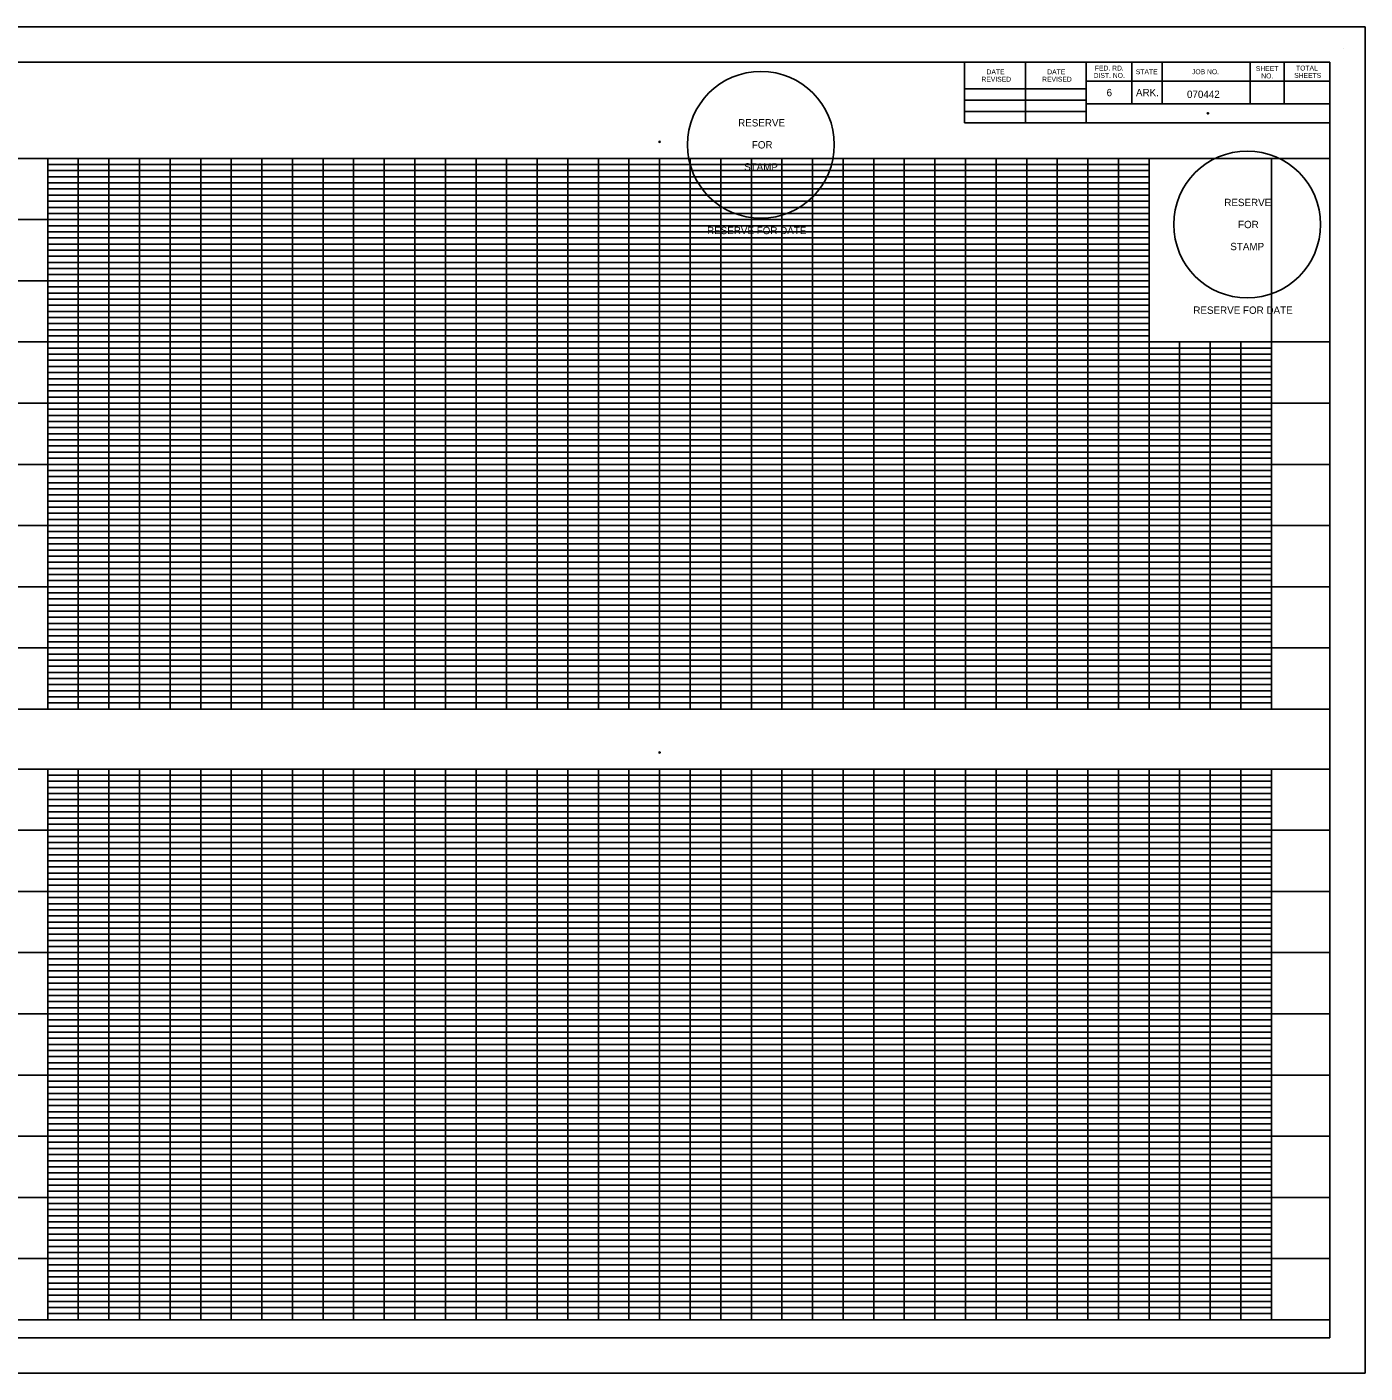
# Model space of a CAD drawing. Extents: x 1 to 1451078, y 0 to 2059437.
# Drawn here: x 1449985 to 1451078, y 2058337 to 2059437 of the extents above; entities that cross this region are included whole.
import ezdxf

# ---------------------------------------------------------------- set-up
doc = ezdxf.new("R2010")
doc.units = 0
for name, color, linetype in [('1', 7, 'Continuous'), ('G-ANNO-TEXT', 7, 'Continuous'), ('G-Border-Sheet', 7, 'Continuous'), ('G-Grid-Border-1', 7, 'Continuous'), ('G-Grid-Border-2', 7, 'Continuous'), ('G-Grid-Major-1', 7, 'Continuous'), ('G-Grid-Minor-1', 7, 'Continuous'), ('G-No Plot-Anchor', 7, 'Continuous'), ('G-No Plot-Stamp-1', 7, 'Continuous'), ('G-No Plot-Stamp-2', 7, 'Continuous'), ('G-Table-Major', 7, 'Continuous'), ('G-Table-Minor', 7, 'Continuous')]:
    doc.layers.add(name, color=color, linetype=linetype)

msp = doc.modelspace()

# ---------------------------------------------------------------- linework, layer by layer
at = {"layer": '1'}
msp.add_lwpolyline([(1451078.1, 2059436.5), (1449378.1, 2059436.5), (1449378.1, 2058336.5), (1451078.1, 2058336.5)], close=True, dxfattribs=at)
at = {"layer": 'G-ANNO-TEXT'}
msp.add_line((1451060.2, 2059419.2), (1451060.2, 2059419.2), dxfattribs=at)
at = {"layer": 'G-Border-Sheet'}
for p, q in [((1449453.9, 2059407.7), (1451049.3, 2059407.7)), ((1451049.3, 2058365.4), (1451049.3, 2059407.7)), ((1451049.3, 2058365.4), (1449453.9, 2058365.4))]:
    msp.add_line(p, q, dxfattribs=at)
at = {"layer": 'G-Grid-Border-1'}
for p, q in [((1450898.5, 2059329.1), (1449453.9, 2059329.1)), ((1451049.3, 2058879.1), (1449453.9, 2058879.1)), ((1451049.3, 2058830.1), (1449453.9, 2058830.1)), ((1451049.3, 2058380.1), (1449453.9, 2058380.1))]:
    msp.add_line(p, q, dxfattribs=at)
for points in [[(1450001.6, 2059329.1), (1450901.6, 2059329.1), (1450901.6, 2059179.1), (1451001.6, 2059179.1), (1451001.6, 2058879.1), (1450001.6, 2058879.1)], [(1450001.6, 2058830.1), (1451001.6, 2058830.1), (1451001.6, 2058380.1), (1450001.6, 2058380.1)]]:
    msp.add_lwpolyline(points, close=True, dxfattribs=at)
at = {"layer": 'G-Grid-Border-2'}
for p, q in [((1450501.6, 2059329.1), (1449453.9, 2059329.1)), ((1450501.6, 2059254.1), (1450501.6, 2059329.1)), ((1450501.6, 2059254.1), (1450501.6, 2059329.1)), ((1450651.6, 2059254.1), (1450651.6, 2059329.1)), ((1451049.3, 2059329.1), (1450651.6, 2059329.1)), ((1450651.6, 2059254.1), (1450651.6, 2059329.1)), ((1450501.6, 2059254.1), (1450651.6, 2059254.1)), ((1450501.6, 2059254.1), (1450651.6, 2059254.1)), ((1451001.6, 2058879.1), (1451001.6, 2059179.1)), ((1451049.3, 2058879.1), (1449453.9, 2058879.1)), ((1451049.3, 2058830.1), (1449453.9, 2058830.1)), ((1451001.6, 2058380.1), (1451001.6, 2058830.1)), ((1451049.3, 2058380.1), (1449453.9, 2058380.1))]:
    msp.add_line(p, q, dxfattribs=at)
for points in [[(1450001.6, 2059329.1), (1450501.6, 2059329.1), (1450501.6, 2059254.1), (1450651.6, 2059254.1), (1450651.6, 2059329.1), (1451001.6, 2059329.1), (1451001.6, 2058879.1), (1450001.6, 2058879.1)], [(1450001.6, 2058830.1), (1451001.6, 2058830.1), (1451001.6, 2058380.1), (1450001.6, 2058380.1)]]:
    msp.add_lwpolyline(points, close=True, dxfattribs=at)
msp.add_lwpolyline([(1451001.6, 2058830.1), (1451001.6, 2058380.1), (1449501.6, 2058380.1), (1449501.6, 2058830.1)], dxfattribs=at)
at = {"layer": 'G-Grid-Major-1'}
for p, q in [((1450001.6, 2058879.1), (1450001.6, 2059329.1)), ((1450051.6, 2058879.1), (1450051.6, 2059329.1)), ((1450101.6, 2058879.1), (1450101.6, 2059329.1)), ((1450151.6, 2058879.1), (1450151.6, 2059329.1)), ((1450201.6, 2058879.1), (1450201.6, 2059329.1)), ((1450251.6, 2058879.1), (1450251.6, 2059329.1)), ((1450301.6, 2058879.1), (1450301.6, 2059329.1)), ((1450351.6, 2058879.1), (1450351.6, 2059329.1)), ((1450401.6, 2058879.1), (1450401.6, 2059329.1)), ((1450451.6, 2058879.1), (1450451.6, 2059329.1)), ((1450501.6, 2058879.1), (1450501.6, 2059329.1)), ((1450551.6, 2058879.1), (1450551.6, 2059329.1)), ((1450601.6, 2058879.1), (1450601.6, 2059329.1)), ((1450651.6, 2058879.1), (1450651.6, 2059329.1)), ((1450701.6, 2058879.1), (1450701.6, 2059329.1)), ((1450751.6, 2058879.1), (1450751.6, 2059329.1)), ((1450801.6, 2058879.1), (1450801.6, 2059329.1)), ((1450851.6, 2058879.1), (1450851.6, 2059329.1)), ((1450901.6, 2058879.1), (1450901.6, 2059329.1)), ((1450901.6, 2059279.1), (1449901.6, 2059279.1)), ((1450901.6, 2059229.1), (1449901.6, 2059229.1)), ((1451049.3, 2059179.1), (1449901.6, 2059179.1)), ((1450951.6, 2058879.1), (1450951.6, 2059179.1)), ((1451049.3, 2059129.1), (1449901.6, 2059129.1)), ((1451049.3, 2059079.1), (1449901.6, 2059079.1)), ((1451049.3, 2059029.1), (1449901.6, 2059029.1)), ((1451049.3, 2058979.1), (1449901.6, 2058979.1)), ((1451049.3, 2058929.1), (1449901.6, 2058929.1)), ((1450051.6, 2058380.1), (1450051.6, 2058830.1)), ((1450101.6, 2058380.1), (1450101.6, 2058830.1)), ((1450151.6, 2058380.1), (1450151.6, 2058830.1)), ((1450201.6, 2058380.1), (1450201.6, 2058830.1)), ((1450251.6, 2058380.1), (1450251.6, 2058830.1)), ((1450301.6, 2058380.1), (1450301.6, 2058830.1)), ((1450351.6, 2058380.1), (1450351.6, 2058830.1)), ((1450401.6, 2058380.1), (1450401.6, 2058830.1)), ((1450451.6, 2058380.1), (1450451.6, 2058830.1)), ((1450501.6, 2058380.1), (1450501.6, 2058830.1)), ((1450551.6, 2058380.1), (1450551.6, 2058830.1)), ((1450601.6, 2058380.1), (1450601.6, 2058830.1)), ((1450651.6, 2058380.1), (1450651.6, 2058830.1)), ((1450701.6, 2058380.1), (1450701.6, 2058830.1)), ((1450751.6, 2058380.1), (1450751.6, 2058830.1)), ((1450801.6, 2058380.1), (1450801.6, 2058830.1)), ((1450851.6, 2058380.1), (1450851.6, 2058830.1)), ((1450901.6, 2058380.1), (1450901.6, 2058830.1)), ((1450951.6, 2058380.1), (1450951.6, 2058830.1)), ((1451049.3, 2058780.1), (1449901.6, 2058780.1)), ((1451049.3, 2058730.1), (1449901.6, 2058730.1)), ((1451049.3, 2058680.1), (1449901.6, 2058680.1)), ((1451049.3, 2058630.1), (1449901.6, 2058630.1)), ((1451049.3, 2058580.1), (1449901.6, 2058580.1)), ((1451049.3, 2058530.1), (1449901.6, 2058530.1)), ((1451049.3, 2058480.1), (1449901.6, 2058480.1)), ((1451049.3, 2058430.1), (1449901.6, 2058430.1))]:
    msp.add_line(p, q, dxfattribs=at)
at = {"layer": 'G-Grid-Minor-1'}
for p, q in [((1450901.6, 2059324.1), (1450001.6, 2059324.1)), ((1450026.6, 2058879.1), (1450026.6, 2059329.1)), ((1450076.6, 2058879.1), (1450076.6, 2059329.1)), ((1450126.6, 2058879.1), (1450126.6, 2059329.1)), ((1450176.6, 2058879.1), (1450176.6, 2059329.1)), ((1450226.6, 2058879.1), (1450226.6, 2059329.1)), ((1450276.6, 2058879.1), (1450276.6, 2059329.1)), ((1450326.6, 2058879.1), (1450326.6, 2059329.1)), ((1450376.6, 2058879.1), (1450376.6, 2059329.1)), ((1450426.6, 2058879.1), (1450426.6, 2059329.1)), ((1450476.6, 2058879.1), (1450476.6, 2059329.1)), ((1450526.6, 2058879.1), (1450526.6, 2059329.1)), ((1450576.6, 2058879.1), (1450576.6, 2059329.1)), ((1450626.6, 2058879.1), (1450626.6, 2059329.1)), ((1450676.6, 2058879.1), (1450676.6, 2059329.1)), ((1450726.6, 2058879.1), (1450726.6, 2059329.1)), ((1450776.6, 2058879.1), (1450776.6, 2059329.1)), ((1450826.6, 2058879.1), (1450826.6, 2059329.1)), ((1450876.6, 2058879.1), (1450876.6, 2059329.1)), ((1450901.6, 2059319.1), (1450001.6, 2059319.1)), ((1450901.6, 2059314.1), (1450001.6, 2059314.1)), ((1450901.6, 2059309.1), (1450001.6, 2059309.1)), ((1450901.6, 2059304.1), (1450001.6, 2059304.1)), ((1450901.6, 2059299.1), (1450001.6, 2059299.1)), ((1450901.6, 2059294.1), (1450001.6, 2059294.1)), ((1450901.6, 2059289.1), (1450001.6, 2059289.1)), ((1450901.6, 2059284.1), (1450001.6, 2059284.1)), ((1450901.6, 2059274.1), (1450001.6, 2059274.1)), ((1450901.6, 2059269.1), (1450001.6, 2059269.1)), ((1450901.6, 2059264.1), (1450001.6, 2059264.1)), ((1450901.6, 2059259.1), (1450001.6, 2059259.1)), ((1450901.6, 2059254.1), (1450001.6, 2059254.1)), ((1450901.6, 2059249.1), (1450001.6, 2059249.1)), ((1450901.6, 2059244.1), (1450001.6, 2059244.1)), ((1450901.6, 2059239.1), (1450001.6, 2059239.1)), ((1450901.6, 2059234.1), (1450001.6, 2059234.1)), ((1450901.6, 2059224.1), (1450001.6, 2059224.1)), ((1450901.6, 2059219.1), (1450001.6, 2059219.1)), ((1450901.6, 2059214.1), (1450001.6, 2059214.1)), ((1450901.6, 2059209.1), (1450001.6, 2059209.1)), ((1450901.6, 2059204.1), (1450001.6, 2059204.1)), ((1450901.6, 2059199.1), (1450001.6, 2059199.1)), ((1450901.6, 2059194.1), (1450001.6, 2059194.1)), ((1450901.6, 2059189.1), (1450001.6, 2059189.1)), ((1450901.6, 2059184.1), (1450001.6, 2059184.1)), ((1450926.6, 2058879.1), (1450926.6, 2059179.1)), ((1450976.6, 2058879.1), (1450976.6, 2059179.1)), ((1451001.6, 2059174.1), (1450001.6, 2059174.1)), ((1451001.6, 2059169.1), (1450001.6, 2059169.1)), ((1451001.6, 2059164.1), (1450001.6, 2059164.1)), ((1451001.6, 2059159.1), (1450001.6, 2059159.1)), ((1451001.6, 2059154.1), (1450001.6, 2059154.1)), ((1451001.6, 2059149.1), (1450001.6, 2059149.1)), ((1451001.6, 2059144.1), (1450001.6, 2059144.1)), ((1451001.6, 2059139.1), (1450001.6, 2059139.1)), ((1451001.6, 2059134.1), (1450001.6, 2059134.1)), ((1451001.6, 2059124.1), (1450001.6, 2059124.1)), ((1451001.6, 2059119.1), (1450001.6, 2059119.1)), ((1451001.6, 2059114.1), (1450001.6, 2059114.1)), ((1451001.6, 2059109.1), (1450001.6, 2059109.1)), ((1451001.6, 2059104.1), (1450001.6, 2059104.1)), ((1451001.6, 2059099.1), (1450001.6, 2059099.1)), ((1451001.6, 2059094.1), (1450001.6, 2059094.1)), ((1451001.6, 2059089.1), (1450001.6, 2059089.1)), ((1451001.6, 2059084.1), (1450001.6, 2059084.1)), ((1451001.6, 2059074.1), (1450001.6, 2059074.1)), ((1451001.6, 2059069.1), (1450001.6, 2059069.1)), ((1451001.6, 2059064.1), (1450001.6, 2059064.1)), ((1451001.6, 2059059.1), (1450001.6, 2059059.1)), ((1451001.6, 2059054.1), (1450001.6, 2059054.1)), ((1451001.6, 2059049.1), (1450001.6, 2059049.1)), ((1451001.6, 2059044.1), (1450001.6, 2059044.1)), ((1451001.6, 2059039.1), (1450001.6, 2059039.1)), ((1451001.6, 2059034.1), (1450001.6, 2059034.1)), ((1451001.6, 2059024.1), (1450001.6, 2059024.1)), ((1451001.6, 2059019.1), (1450001.6, 2059019.1)), ((1451001.6, 2059014.1), (1450001.6, 2059014.1)), ((1451001.6, 2059009.1), (1450001.6, 2059009.1)), ((1451001.6, 2059004.1), (1450001.6, 2059004.1)), ((1451001.6, 2058999.1), (1450001.6, 2058999.1)), ((1451001.6, 2058994.1), (1450001.6, 2058994.1)), ((1451001.6, 2058989.1), (1450001.6, 2058989.1)), ((1451001.6, 2058984.1), (1450001.6, 2058984.1)), ((1451001.6, 2058974.1), (1450001.6, 2058974.1)), ((1451001.6, 2058969.1), (1450001.6, 2058969.1)), ((1451001.6, 2058964.1), (1450001.6, 2058964.1)), ((1451001.6, 2058959.1), (1450001.6, 2058959.1)), ((1451001.6, 2058954.1), (1450001.6, 2058954.1)), ((1451001.6, 2058949.1), (1450001.6, 2058949.1)), ((1451001.6, 2058944.1), (1450001.6, 2058944.1)), ((1451001.6, 2058939.1), (1450001.6, 2058939.1)), ((1451001.6, 2058934.1), (1450001.6, 2058934.1)), ((1451001.6, 2058924.1), (1450001.6, 2058924.1)), ((1451001.6, 2058919.1), (1450001.6, 2058919.1)), ((1451001.6, 2058914.1), (1450001.6, 2058914.1)), ((1451001.6, 2058909.1), (1450001.6, 2058909.1)), ((1451001.6, 2058904.1), (1450001.6, 2058904.1)), ((1451001.6, 2058899.1), (1450001.6, 2058899.1)), ((1451001.6, 2058894.1), (1450001.6, 2058894.1)), ((1451001.6, 2058889.1), (1450001.6, 2058889.1)), ((1451001.6, 2058884.1), (1450001.6, 2058884.1)), ((1450026.6, 2058380.1), (1450026.6, 2058830.1)), ((1450076.6, 2058380.1), (1450076.6, 2058830.1)), ((1450126.6, 2058380.1), (1450126.6, 2058830.1)), ((1450176.6, 2058380.1), (1450176.6, 2058830.1)), ((1450226.6, 2058380.1), (1450226.6, 2058830.1)), ((1450276.6, 2058380.1), (1450276.6, 2058830.1)), ((1450326.6, 2058380.1), (1450326.6, 2058830.1)), ((1450376.6, 2058380.1), (1450376.6, 2058830.1)), ((1450426.6, 2058380.1), (1450426.6, 2058830.1)), ((1450476.6, 2058380.1), (1450476.6, 2058830.1)), ((1450526.6, 2058380.1), (1450526.6, 2058830.1)), ((1450576.6, 2058380.1), (1450576.6, 2058830.1)), ((1450626.6, 2058380.1), (1450626.6, 2058830.1)), ((1450676.6, 2058380.1), (1450676.6, 2058830.1)), ((1450726.6, 2058380.1), (1450726.6, 2058830.1)), ((1450776.6, 2058380.1), (1450776.6, 2058830.1)), ((1450826.6, 2058380.1), (1450826.6, 2058830.1)), ((1450876.6, 2058380.1), (1450876.6, 2058830.1)), ((1450926.6, 2058380.1), (1450926.6, 2058830.1)), ((1450976.6, 2058380.1), (1450976.6, 2058830.1)), ((1451001.6, 2058825.1), (1450001.6, 2058825.1)), ((1451001.6, 2058820.1), (1450001.6, 2058820.1)), ((1451001.6, 2058815.1), (1450001.6, 2058815.1)), ((1451001.6, 2058810.1), (1450001.6, 2058810.1)), ((1451001.6, 2058805.1), (1450001.6, 2058805.1)), ((1451001.6, 2058800.1), (1450001.6, 2058800.1)), ((1451001.6, 2058795.1), (1450001.6, 2058795.1)), ((1451001.6, 2058790.1), (1450001.6, 2058790.1)), ((1451001.6, 2058785.1), (1450001.6, 2058785.1)), ((1451001.6, 2058775.1), (1450001.6, 2058775.1)), ((1451001.6, 2058770.1), (1450001.6, 2058770.1)), ((1451001.6, 2058765.1), (1450001.6, 2058765.1)), ((1451001.6, 2058760.1), (1450001.6, 2058760.1)), ((1451001.6, 2058755.1), (1450001.6, 2058755.1)), ((1451001.6, 2058750.1), (1450001.6, 2058750.1)), ((1451001.6, 2058745.1), (1450001.6, 2058745.1)), ((1451001.6, 2058740.1), (1450001.6, 2058740.1)), ((1451001.6, 2058735.1), (1450001.6, 2058735.1)), ((1451001.6, 2058725.1), (1450001.6, 2058725.1)), ((1451001.6, 2058720.1), (1450001.6, 2058720.1)), ((1451001.6, 2058715.1), (1450001.6, 2058715.1)), ((1451001.6, 2058710.1), (1450001.6, 2058710.1)), ((1451001.6, 2058705.1), (1450001.6, 2058705.1)), ((1451001.6, 2058700.1), (1450001.6, 2058700.1)), ((1451001.6, 2058695.1), (1450001.6, 2058695.1)), ((1451001.6, 2058690.1), (1450001.6, 2058690.1)), ((1451001.6, 2058685.1), (1450001.6, 2058685.1)), ((1451001.6, 2058675.1), (1450001.6, 2058675.1)), ((1451001.6, 2058670.1), (1450001.6, 2058670.1)), ((1451001.6, 2058665.1), (1450001.6, 2058665.1)), ((1451001.6, 2058660.1), (1450001.6, 2058660.1)), ((1451001.6, 2058655.1), (1450001.6, 2058655.1)), ((1451001.6, 2058650.1), (1450001.6, 2058650.1)), ((1451001.6, 2058645.1), (1450001.6, 2058645.1)), ((1451001.6, 2058640.1), (1450001.6, 2058640.1)), ((1451001.6, 2058635.1), (1450001.6, 2058635.1)), ((1451001.6, 2058625.1), (1450001.6, 2058625.1)), ((1451001.6, 2058620.1), (1450001.6, 2058620.1)), ((1451001.6, 2058615.1), (1450001.6, 2058615.1)), ((1451001.6, 2058610.1), (1450001.6, 2058610.1)), ((1451001.6, 2058605.1), (1450001.6, 2058605.1)), ((1451001.6, 2058600.1), (1450001.6, 2058600.1)), ((1451001.6, 2058595.1), (1450001.6, 2058595.1)), ((1451001.6, 2058590.1), (1450001.6, 2058590.1)), ((1451001.6, 2058585.1), (1450001.6, 2058585.1)), ((1451001.6, 2058575.1), (1450001.6, 2058575.1)), ((1451001.6, 2058570.1), (1450001.6, 2058570.1)), ((1451001.6, 2058565.1), (1450001.6, 2058565.1)), ((1451001.6, 2058560.1), (1450001.6, 2058560.1)), ((1451001.6, 2058555.1), (1450001.6, 2058555.1)), ((1451001.6, 2058550.1), (1450001.6, 2058550.1)), ((1451001.6, 2058545.1), (1450001.6, 2058545.1)), ((1451001.6, 2058540.1), (1450001.6, 2058540.1)), ((1451001.6, 2058535.1), (1450001.6, 2058535.1)), ((1451001.6, 2058525.1), (1450001.6, 2058525.1)), ((1451001.6, 2058520.1), (1450001.6, 2058520.1)), ((1451001.6, 2058515.1), (1450001.6, 2058515.1)), ((1451001.6, 2058510.1), (1450001.6, 2058510.1)), ((1451001.6, 2058505.1), (1450001.6, 2058505.1)), ((1451001.6, 2058500.1), (1450001.6, 2058500.1)), ((1451001.6, 2058495.1), (1450001.6, 2058495.1)), ((1451001.6, 2058490.1), (1450001.6, 2058490.1)), ((1451001.6, 2058485.1), (1450001.6, 2058485.1)), ((1451001.6, 2058475.1), (1450001.6, 2058475.1)), ((1451001.6, 2058470.1), (1450001.6, 2058470.1)), ((1451001.6, 2058465.1), (1450001.6, 2058465.1)), ((1451001.6, 2058460.1), (1450001.6, 2058460.1)), ((1451001.6, 2058455.1), (1450001.6, 2058455.1)), ((1451001.6, 2058450.1), (1450001.6, 2058450.1)), ((1451001.6, 2058445.1), (1450001.6, 2058445.1)), ((1451001.6, 2058440.1), (1450001.6, 2058440.1)), ((1451001.6, 2058435.1), (1450001.6, 2058435.1)), ((1451001.6, 2058425.1), (1450001.6, 2058425.1)), ((1451001.6, 2058420.1), (1450001.6, 2058420.1)), ((1451001.6, 2058415.1), (1450001.6, 2058415.1)), ((1451001.6, 2058410.1), (1450001.6, 2058410.1)), ((1451001.6, 2058405.1), (1450001.6, 2058405.1)), ((1451001.6, 2058400.1), (1450001.6, 2058400.1)), ((1451001.6, 2058395.1), (1450001.6, 2058395.1)), ((1451001.6, 2058390.1), (1450001.6, 2058390.1)), ((1451001.6, 2058385.1), (1450001.6, 2058385.1))]:
    msp.add_line(p, q, dxfattribs=at)
msp.add_lwpolyline([(1451001.6, 2059179.1), (1451001.6, 2058879.1), (1449501.6, 2058879.1), (1449501.6, 2059329.1)], dxfattribs=at)
at = {"layer": 'G-No Plot-Anchor'}
for centre in [(1450949.7, 2059365.9), (1450501.6, 2059342.6), (1450501.6, 2058843.6)]:
    msp.add_circle(centre, 0.5, dxfattribs=at)
at = {"layer": 'G-No Plot-Stamp-1'}
msp.add_line((1451001.6, 2058879.1), (1450001.6, 2058879.1), dxfattribs=at)
msp.add_circle((1450981.8, 2059275.1), 60, dxfattribs=at)
at = {"layer": 'G-No Plot-Stamp-2'}
msp.add_circle((1450584.4, 2059340.2), 60, dxfattribs=at)
at = {"layer": 'G-Table-Major'}
for p, q in [((1450750.9, 2059358.2), (1450750.9, 2059407.7)), ((1450850.2, 2059407.7), (1450850.2, 2059358.1)), ((1450750.9, 2059386), (1450850.2, 2059386)), ((1451049.3, 2059358.1), (1450750.9, 2059358.1))]:
    msp.add_line(p, q, dxfattribs=at)
at = {"layer": 'G-Table-Minor'}
for p, q in [((1450800.7, 2059358.2), (1450800.7, 2059407.7)), ((1450887.4, 2059407.7), (1450887.4, 2059373.7)), ((1450912.2, 2059407.7), (1450912.2, 2059373.7)), ((1450984.3, 2059407.7), (1450984.3, 2059373.7)), ((1451012.1, 2059407.7), (1451012.1, 2059373.7)), ((1451049.3, 2059392.1), (1450850.2, 2059392.1)), ((1451049.3, 2059393.1), (1451049.3, 2059393.1)), ((1450750.9, 2059376.6), (1450850.2, 2059376.6)), ((1450750.9, 2059367.5), (1450850.2, 2059367.5)), ((1451049.3, 2059373.7), (1450850.2, 2059373.7))]:
    msp.add_line(p, q, dxfattribs=at)

# ---------------------------------------------------------------- texts
at = {"layer": 'G-ANNO-TEXT'}
for s, height, p in [('DATE', 4, (1450768.8, 2059397.8)), ('DATE', 4, (1450818.4, 2059397.8)), ('DIST. NO.', 4, (1450856.3, 2059394.9)), ('FED. RD.', 4, (1450857.3, 2059400.9)), ('STATE', 4, (1450890.8, 2059397.9)), ('JOB NO.', 4, (1450936.7, 2059397.9)), ('SHEET', 4, (1450988.9, 2059400.5)), ('NO.', 4, (1450993.3, 2059394.5)), ('SHEETS', 4, (1451020.2, 2059394.9)), ('TOTAL', 4, (1451021.7, 2059400.9)), ('REVISED', 4, (1450764.6, 2059391.8)), ('REVISED', 4, (1450814.2, 2059391.8)), ('6', 6, (1450866.9, 2059379.9)), ('ARK.', 6, (1450890.9, 2059379.9)), ('070442', 6, (1450932.6, 2059378.5))]:
    msp.add_text(s, height=height, dxfattribs=at).set_placement(p)
at = {"layer": 'G-No Plot-Stamp-1'}
for s, p in [('RESERVE', (1450963.1, 2059290.1)), ('FOR ', (1450974.3, 2059272.1)), ('STAMP', (1450968, 2059254.1)), ('RESERVE FOR DATE', (1450937.8, 2059202.1))]:
    msp.add_text(s, height=6, dxfattribs=at).set_placement(p)
at = {"layer": 'G-No Plot-Stamp-2'}
for s, p in [('RESERVE', (1450565.8, 2059355.2)), ('FOR ', (1450577, 2059337.2)), ('STAMP', (1450570.7, 2059319.2)), ('RESERVE FOR DATE', (1450540.4, 2059267.2)), ('RESERVE FOR DATE', (1450540.4, 2059267.2))]:
    msp.add_text(s, height=6, dxfattribs=at).set_placement(p)

doc.saveas('drawing.dxf')
